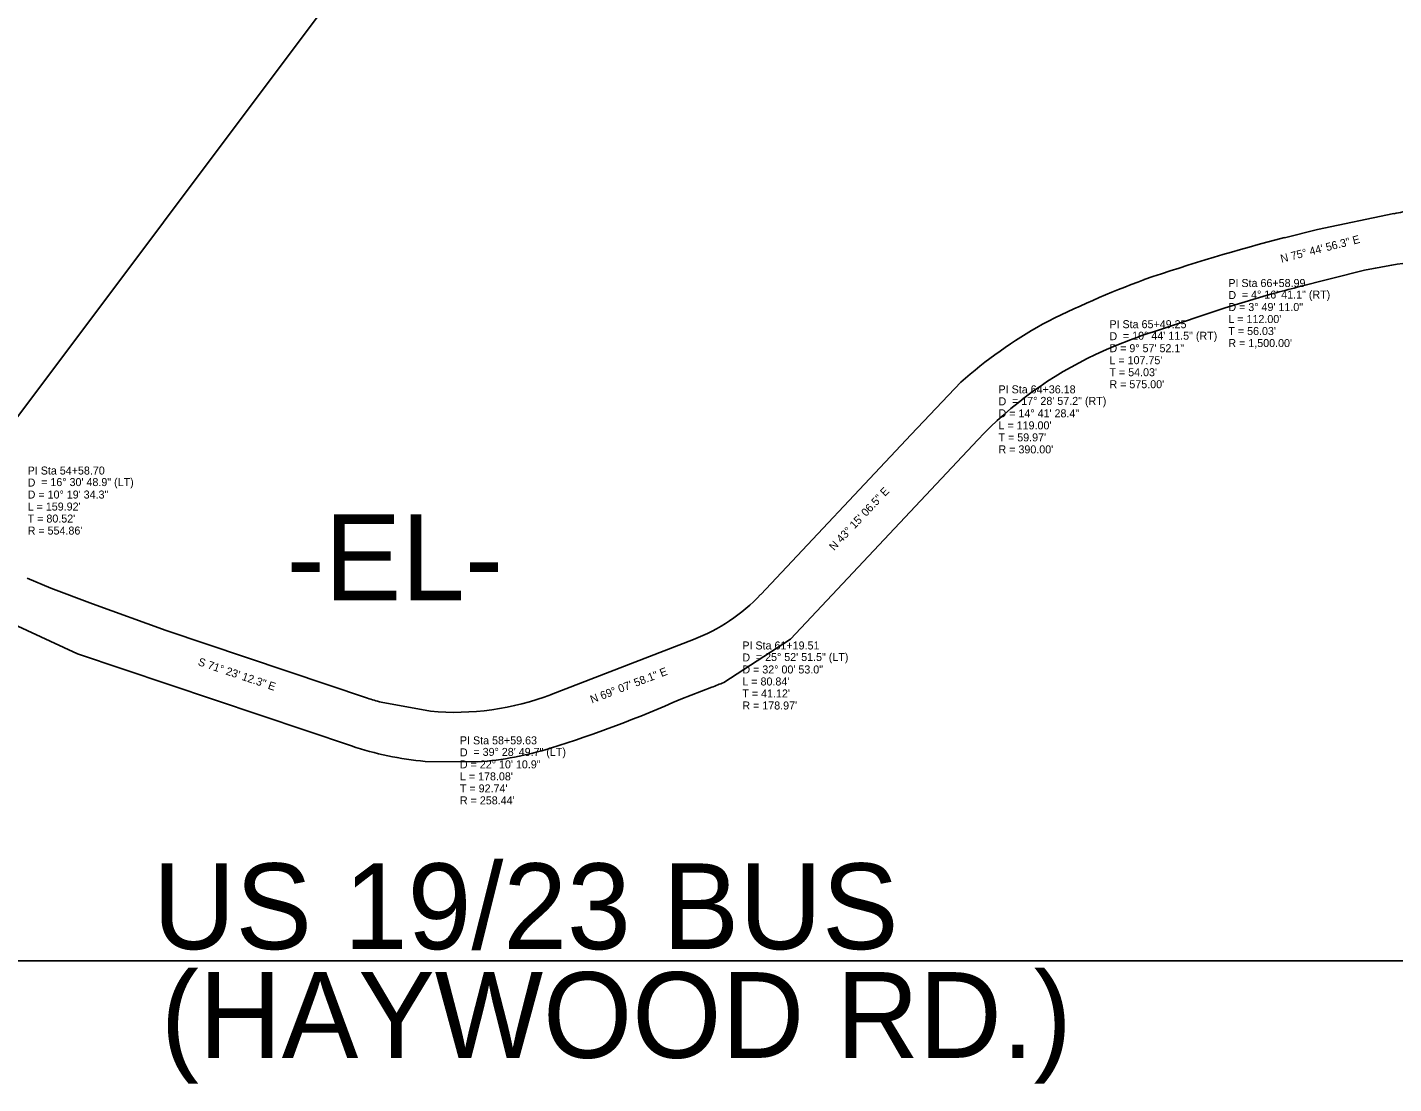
# Model space of a CAD drawing. Extents: x 925297 to 940193, y 663541 to 689899.
# Drawn here: x 931902 to 933097, y 684100 to 685024 of the extents above; entities that cross this region are included whole.
import ezdxf

# ---------------------------------------------------------------- set-up
doc = ezdxf.new("R2010")
doc.units = 0
for name, color, linetype in [('Default', 7, 'Continuous'), ('Exist Horizontal Alignment Curve and Spiral Data', 7, 'Continuous'), ('Exist Horizontal Alignment Direction Label', 7, 'Continuous'), ('Prop DSN Text', 7, 'Continuous'), ('Prop Shade Light', 7, 'Continuous')]:
    doc.layers.add(name, color=color, linetype=linetype)

msp = doc.modelspace()

# ---------------------------------------------------------------- linework, layer by layer
at = {"layer": 'Default'}
for p, q in [((931536.9, 684208.3), (932166.5, 685048.6)), ((931719.8, 684207.7), (933219.8, 684207.7))]:
    msp.add_line(p, q, dxfattribs=at)
at = {"layer": 'Prop Shade Light'}
for p, q in [((933029.8, 684847.4), (933096.6, 684861.2)), ((933001.2, 684840.1), (933029.8, 684847.4)), ((933071, 684811.8), (933012.2, 684796.8)), ((932991, 684791.3), (932949.1, 684778.7)), ((932949.1, 684778.7), (932889.2, 684758.7)), ((932674.6, 684667.9), (932717.9, 684713.7)), ((932543, 684528.1), (932674.6, 684667.9)), ((932732.8, 684663.3), (932569, 684489.1)), ((931901.7, 684542.3), (931922.2, 684533.7)), ((931922.2, 684533.7), (931958.7, 684519.8)), ((931958.7, 684519.8), (932023.1, 684496.7)), ((931945.7, 684476.3), (931889.7, 684502.2)), ((932023.1, 684496.7), (932199.2, 684437.4)), ((932359.9, 684440.6), (932484.3, 684488.8)), ((932569, 684489.1), (932510.7, 684451.2)), ((932185.1, 684395.6), (931945.7, 684476.3)), ((932500.3, 684446.9), (932473.1, 684436.5)), ((932211, 684433.8), (932254.2, 684425.9)), ((932295.6, 684381.6), (932249.5, 684382))]:
    msp.add_line(p, q, dxfattribs=at)
for centre, radius, start, end in [((933088.7, 684918.2), 57.6, 277.8498, 294.3272), ((933375.6, 683365.9), 1521.1, 104.251, 109.0754), ((933191.1, 684236.8), 587.3, 94.216, 101.7942), ((933149.4, 684062.4), 789, 110.0793, 117.146), ((933376.1, 683364.4), 1477.9, 104.251, 105.1026), ((932991.2, 684404.3), 412.8, 119.2656, 131.452), ((933021.1, 684341.6), 437.5, 107.5527, 115.0668), ((932978.6, 684432.3), 337.3, 115.0453, 136.7666), ((932428.1, 684636.1), 157.7, 290.8672, 316.7482), ((932428.1, 684636.1), 202.5, 290.8672, 294.0577), ((932275.2, 684662.9), 237.9, 251.3867, 254.3498), ((932275.2, 684662.9), 237.9, 264.9505, 290.8672), ((932047.5, 685395.1), 1048.8, 287.2973, 293.9404), ((932275.2, 684662.9), 282, 251.3867, 264.7749), ((932275.2, 684662.9), 282, 274.1633, 287.3645)]:
    msp.add_arc(centre, radius, start, end, dxfattribs=at)

# ---------------------------------------------------------------- texts
at = {"layer": 'Exist Horizontal Alignment Curve and Spiral Data'}
for s, p in [('PI Sta 66+58.99', (932952, 684797)), ('D', (932952, 684786.5)), ('D = 3%%d 49\' 11.0"', (932952, 684776)), ('= 4%%d 16\' 41.1" (RT)', (932963.8, 684786.9)), ("L = 112.00'", (932952, 684765.5)), ('PI Sta 65+49.25', (932848, 684761)), ("T = 56.03'", (932952, 684755)), ('D', (932848, 684750.5)), ('D = 9%%d 57\' 52.1"', (932848, 684740)), ('= 10%%d 44\' 11.5" (RT)', (932859.8, 684750.9)), ("R = 1,500.00'", (932952, 684744.5)), ("L = 107.75'", (932848, 684729.5)), ("T = 54.03'", (932848, 684719)), ("R = 575.00'", (932848, 684708.5)), ('PI Sta 64+36.18', (932751, 684704)), ('D', (932751, 684693.5)), ('= 17%%d 28\' 57.2" (RT)', (932762.8, 684693.9)), ('D = 14%%d 41\' 28.4"', (932751, 684683)), ("L = 119.00'", (932751, 684672.5)), ("T = 59.97'", (932751, 684662)), ("R = 390.00'", (932751, 684651.5)), ('PI Sta 54+58.70', (931902, 684633)), ('D', (931902, 684622.5)), ('= 16%%d 30\' 48.9" (LT)', (931913.8, 684622.9)), ('D = 10%%d 19\' 34.3"', (931902, 684612)), ("L = 159.92'", (931902, 684601.5)), ("T = 80.52'", (931902, 684591)), ("R = 554.86'", (931902, 684580.5)), ('PI Sta 61+19.51', (932527, 684480)), ('D', (932527, 684469.5)), ('= 25%%d 52\' 51.5" (LT)', (932538.8, 684469.9)), ('D = 32%%d 00\' 53.0"', (932527, 684459)), ("L = 80.84'", (932527, 684448.5)), ("T = 41.12'", (932527, 684438)), ("R = 178.97'", (932527, 684427.5)), ('PI Sta 58+59.63', (932280, 684397)), ('D', (932280, 684386.5)), ('= 39%%d 28\' 49.7" (LT)', (932291.8, 684386.9)), ('D = 22%%d 10\' 10.9"', (932280, 684376)), ("L = 178.08'", (932280, 684365.5)), ("T = 92.74'", (932280, 684355)), ("R = 258.44'", (932280, 684344.5))]:
    msp.add_text(s, height=7, dxfattribs=at).set_placement(p)
at = {"layer": 'Exist Horizontal Alignment Direction Label'}
for s, rotation, p in [('N 75%%d 44\' 56.3" E', 14.251, (932998.5, 684818.2)), ('N 43%%d 15\' 06.5" E', 46.7482, (932607.2, 684566)), ('S 71%%d 23\' 12.3" E', 341.3867, (932050.4, 684466.4)), ('N 69%%d 07\' 58.1" E', 20.8672, (932395.5, 684432.7))]:
    msp.add_text(s, height=7, rotation=rotation, dxfattribs=at).set_placement(p)
at = {"layer": 'Prop DSN Text'}
for s, p in [('-EL-', (932128.3, 684523.1)), ('US 19/23 BUS ', (932011.3, 684217.9)), ('(HAYWOOD RD.)', (932018.4, 684122.8))]:
    msp.add_text(s, height=75, rotation=360, dxfattribs=at).set_placement(p)

doc.saveas('drawing.dxf')
